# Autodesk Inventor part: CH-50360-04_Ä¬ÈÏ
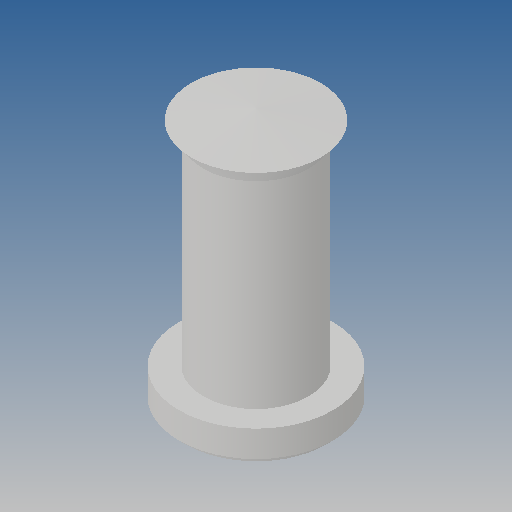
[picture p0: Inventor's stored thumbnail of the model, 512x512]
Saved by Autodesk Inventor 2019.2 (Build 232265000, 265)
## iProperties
Created: 2010-06
Part Number: CH-50360-04_Ä¬ÈÏ
Material: Ogólny
Document SubType Name: Modeling
Designer: CADENGINEERING4
Density: 1 g/cm^3
Appearance: Domyślna
Author: CADENGINEERING4
Revision Number: ÈÎºÎ
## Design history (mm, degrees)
feature "NONE"
node "Bryła1"
